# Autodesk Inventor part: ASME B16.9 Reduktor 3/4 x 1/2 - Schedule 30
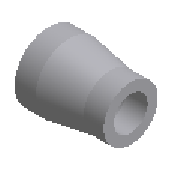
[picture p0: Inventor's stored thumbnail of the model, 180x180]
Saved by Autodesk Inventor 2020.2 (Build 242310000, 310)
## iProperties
Manager: www.cadconsulting.pl
Company: Fabian Stasiak CAD Consulting
Created: 2014-02
Part Number: ASME B16.9 Reduktor 3/4 x 1/2 - Schedule 30
Material: Stal kuta
Description: Element kuty, spawany doczołowo - Reduktor .calowy
Document SubType Name: Modeling
Standard: ASME B16.9
Designer: F.Stasiak
Standard Revision: 2003
Standards Organization: ANSI
Language: pl-PL
Size Designation: 3/4 x 1/2 - Schedule 30
Categories: <MemberInstance><Categories><Category DisplayName="Rury cienko- i grubościenne" InternalName="4347fa0f-2144-441d-94cd-e3e15c92b736" Mnemonic="TUBEANDPIPE"><Cate
Density: 1 g/cm^3
Appearance: Stal
Catalog Web Link: www.expertbooks.pl
NAME: PIPING: ASME B16.9 Reducer
DATA: <meta><inlinegroups number="1" deflen="5.08"></inlinegroups><connections number="2"></connections><angles><a>3.14159265358979</a></angles></meta>
IsCustomPart: 0
Author: F.Stasiak
Subject: Zbiór ćwiczeń. Autodesk Inventor 2020. Kurs Professional
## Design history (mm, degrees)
sketch "Sketch1"
  geometry: L1 (0, 13.335)-(-9.525, 13.335); L2 (-9.525, 13.335)-(-28.575, 10.668); L3 (-28.575, 10.668)-(-38.1, 10.668); L4 (-38.1, 0)-(0, 0); L5 (-38.1, 8.255)-(-28.407, 8.255); L6 (-28.407, 8.255)-(-9.357, 10.922); L7 (-9.357, 10.922)-(0, 10.922); L8 (-38.1, 0)-(-38.1, 8.255); L9 (-38.1, 10.668)-(-38.1, 8.255); L10 (0, 13.335)-(0, 10.922); L11 (0, 0)-(0, 10.922)
  constraints: 22 end point, 6 parallel, 2 collinear, 1 horizontal, 1 perpendicular, 1 other
  dimensions: "d0" = 26.67 diameter of L1.start L4 (= OD1); "d1" = 21.336 diameter of L3.end L4 (= OD2); "d2" = 2.413 distance of L1.start L7.end (= T1); "d3" = 2.413 distance of L3.end L5.start (= T2); "d4" = 38.1 distance between parallel lines of L11 L8 (= H); "d5" = 9.525 distance from line of L2.end L9 (= 0.25 x H); "d6" = 9.525 distance of L1.start L1.end (= 0.25 x H); "d7" = 2.413 distance between parallel lines of L2 L6 (= T1)
revolve "Revolution1" sketch "Sketch1" stored, may be unused: angle "d9" = 90 deg
workaxis "Work Axis1"
workpoint "Work Point1"
workaxis "Work Axis2"
workpoint "Work Point2"
body "Solid1"
other parameters: "T1" = 2.413 [user parameter; used in 2 equation terms], "OD1" = 26.67 [user parameter; used in 1 equation term], "OD2" = 21.336 [user parameter; used in 1 equation term], "H" = 38.1 [user parameter; used in 3 equation terms], "T2" = 2.413 [user parameter; used in 1 equation term], "Size_Designation" = 12.345 [user parameter]
